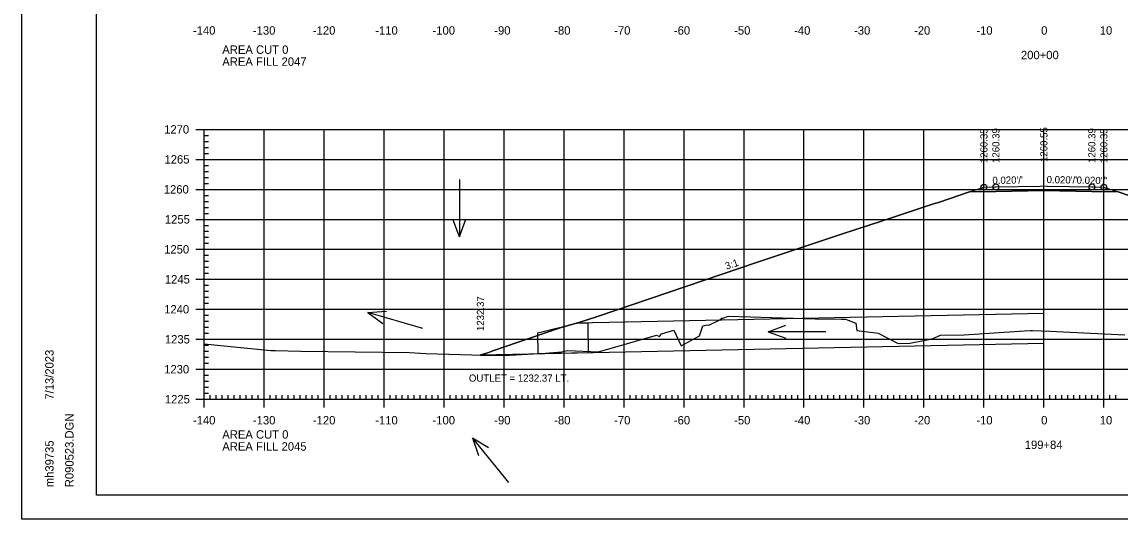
# Model space of a CAD drawing. Extents: x 1406028 to 1412453, y 321733 to 325986.
# Drawn here: x 1408884.4 to 1409067.5, y 322056.2 to 322139.1 of the extents above; entities that cross this region are included whole.
import ezdxf

# ---------------------------------------------------------------- set-up
doc = ezdxf.new("R2010")
doc.units = 0
for name, color, linetype in [('1', 7, 'Continuous'), ('R_Alt Surface', 7, 'Continuous'), ('R_Axis', 7, 'Continuous'), ('R_Axis Annot', 7, 'Continuous'), ('R_Border', 7, 'Continuous'), ('R_Exist Surface', 7, 'Continuous'), ('R_Fin Surface', 7, 'Continuous'), ('R_Fin Surface Annot', 7, 'Continuous'), ('R_Grid', 7, 'Continuous'), ('R_Horz Alg Annot', 7, 'Continuous'), ('R_No Plot', 7, 'Continuous'), ('R_Water', 7, 'Continuous'), ('R_Water Annot', 7, 'Continuous')]:
    doc.layers.add(name, color=color, linetype=linetype)

msp = doc.modelspace()

# ---------------------------------------------------------------- linework, layer by layer
at = {"layer": '1'}
msp.add_lwpolyline([(1408978.74, 322088.95), (1408978.84, 322083.95), (1408970.51, 322083.78), (1408970.44, 322087.28), (1408976.91, 322088.91)], close=True, dxfattribs=at)
at = {"layer": 'R_Alt Surface'}
msp.add_lwpolyline([(1409042.42, 322110.77), (1409046.81, 322110.86), (1409054.81, 322111.02), (1409062.81, 322110.86), (1409067.21, 322110.77)], dxfattribs=at)
at = {"layer": 'R_Axis'}
for p, q in [((1408913.41, 322121.21), (1408916.21, 322121.21)), ((1408914.81, 322076.21), (1408914.81, 322121.21)), ((1408914.81, 322120.21), (1408915.51, 322120.21)), ((1408914.81, 322119.21), (1408915.51, 322119.21)), ((1408914.81, 322118.21), (1408915.51, 322118.21)), ((1408914.81, 322117.21), (1408915.51, 322117.21)), ((1408913.41, 322116.21), (1408916.21, 322116.21)), ((1408914.81, 322115.21), (1408915.51, 322115.21)), ((1408914.81, 322114.21), (1408915.51, 322114.21)), ((1408914.81, 322113.21), (1408915.51, 322113.21)), ((1408914.81, 322112.21), (1408915.51, 322112.21)), ((1408913.41, 322111.21), (1408916.21, 322111.21)), ((1408914.81, 322110.21), (1408915.51, 322110.21)), ((1408914.81, 322109.21), (1408915.51, 322109.21)), ((1408914.81, 322108.21), (1408915.51, 322108.21)), ((1408913.41, 322106.21), (1408916.21, 322106.21)), ((1408914.81, 322107.21), (1408915.51, 322107.21)), ((1408914.81, 322105.21), (1408915.51, 322105.21)), ((1408914.81, 322104.21), (1408915.51, 322104.21)), ((1408914.81, 322103.21), (1408915.51, 322103.21)), ((1408913.41, 322101.21), (1408916.21, 322101.21)), ((1408914.81, 322102.21), (1408915.51, 322102.21)), ((1408914.81, 322100.21), (1408915.51, 322100.21)), ((1408914.81, 322099.21), (1408915.51, 322099.21)), ((1408914.81, 322098.21), (1408915.51, 322098.21)), ((1408914.81, 322097.21), (1408915.51, 322097.21)), ((1408913.41, 322096.21), (1408916.21, 322096.21)), ((1408914.81, 322095.21), (1408915.51, 322095.21)), ((1408914.81, 322094.21), (1408915.51, 322094.21)), ((1408914.81, 322093.21), (1408915.51, 322093.21)), ((1408914.81, 322092.21), (1408915.51, 322092.21)), ((1408913.41, 322091.21), (1408916.21, 322091.21)), ((1408914.81, 322090.21), (1408915.51, 322090.21)), ((1408914.81, 322089.21), (1408915.51, 322089.21)), ((1408914.81, 322088.21), (1408915.51, 322088.21)), ((1408913.41, 322086.21), (1408916.21, 322086.21)), ((1408914.81, 322087.21), (1408915.51, 322087.21)), ((1408914.81, 322085.21), (1408915.51, 322085.21)), ((1408914.81, 322084.21), (1408915.51, 322084.21)), ((1408914.81, 322083.21), (1408915.51, 322083.21)), ((1408913.41, 322081.21), (1408916.21, 322081.21)), ((1408914.81, 322082.21), (1408915.51, 322082.21)), ((1408914.81, 322080.21), (1408915.51, 322080.21)), ((1408914.81, 322079.21), (1408915.51, 322079.21)), ((1408914.81, 322078.21), (1408915.51, 322078.21)), ((1408914.81, 322074.81), (1408914.81, 322077.61)), ((1408914.81, 322077.21), (1408915.51, 322077.21)), ((1408915.81, 322076.21), (1408915.81, 322076.91)), ((1408916.81, 322076.21), (1408916.81, 322076.91)), ((1408917.81, 322076.21), (1408917.81, 322076.91)), ((1408918.81, 322076.21), (1408918.81, 322076.91)), ((1408919.81, 322076.21), (1408919.81, 322076.91)), ((1408920.81, 322076.21), (1408920.81, 322076.91)), ((1408921.81, 322076.21), (1408921.81, 322076.91)), ((1408922.81, 322076.21), (1408922.81, 322076.91)), ((1408923.81, 322076.21), (1408923.81, 322076.91)), ((1408924.81, 322074.81), (1408924.81, 322077.61)), ((1408925.81, 322076.21), (1408925.81, 322076.91)), ((1408926.81, 322076.21), (1408926.81, 322076.91)), ((1408927.81, 322076.21), (1408927.81, 322076.91)), ((1408928.81, 322076.21), (1408928.81, 322076.91)), ((1408929.81, 322076.21), (1408929.81, 322076.91)), ((1408930.81, 322076.21), (1408930.81, 322076.91)), ((1408931.81, 322076.21), (1408931.81, 322076.91)), ((1408932.81, 322076.21), (1408932.81, 322076.91)), ((1408933.81, 322076.21), (1408933.81, 322076.91)), ((1408934.81, 322074.81), (1408934.81, 322077.61)), ((1408935.81, 322076.21), (1408935.81, 322076.91)), ((1408936.81, 322076.21), (1408936.81, 322076.91)), ((1408937.81, 322076.21), (1408937.81, 322076.91)), ((1408938.81, 322076.21), (1408938.81, 322076.91)), ((1408939.81, 322076.21), (1408939.81, 322076.91)), ((1408940.81, 322076.21), (1408940.81, 322076.91)), ((1408941.81, 322076.21), (1408941.81, 322076.91)), ((1408942.81, 322076.21), (1408942.81, 322076.91)), ((1408943.81, 322076.21), (1408943.81, 322076.91)), ((1408944.81, 322074.81), (1408944.81, 322077.61)), ((1408945.81, 322076.21), (1408945.81, 322076.91)), ((1408946.81, 322076.21), (1408946.81, 322076.91)), ((1408947.81, 322076.21), (1408947.81, 322076.91)), ((1408948.81, 322076.21), (1408948.81, 322076.91)), ((1408949.81, 322076.21), (1408949.81, 322076.91)), ((1408950.81, 322076.21), (1408950.81, 322076.91)), ((1408951.81, 322076.21), (1408951.81, 322076.91)), ((1408952.81, 322076.21), (1408952.81, 322076.91)), ((1408953.81, 322076.21), (1408953.81, 322076.91)), ((1408954.81, 322074.81), (1408954.81, 322077.61)), ((1408955.81, 322076.21), (1408955.81, 322076.91)), ((1408956.81, 322076.21), (1408956.81, 322076.91)), ((1408957.81, 322076.21), (1408957.81, 322076.91)), ((1408958.81, 322076.21), (1408958.81, 322076.91)), ((1408959.81, 322076.21), (1408959.81, 322076.91)), ((1408960.81, 322076.21), (1408960.81, 322076.91)), ((1408961.81, 322076.21), (1408961.81, 322076.91)), ((1408962.81, 322076.21), (1408962.81, 322076.91)), ((1408963.81, 322076.21), (1408963.81, 322076.91)), ((1408964.81, 322074.81), (1408964.81, 322077.61)), ((1408965.81, 322076.21), (1408965.81, 322076.91)), ((1408966.81, 322076.21), (1408966.81, 322076.91)), ((1408967.81, 322076.21), (1408967.81, 322076.91)), ((1408968.81, 322076.21), (1408968.81, 322076.91)), ((1408969.81, 322076.21), (1408969.81, 322076.91)), ((1408970.81, 322076.21), (1408970.81, 322076.91)), ((1408971.81, 322076.21), (1408971.81, 322076.91)), ((1408972.81, 322076.21), (1408972.81, 322076.91)), ((1408973.81, 322076.21), (1408973.81, 322076.91)), ((1408974.81, 322074.81), (1408974.81, 322077.61)), ((1408975.81, 322076.21), (1408975.81, 322076.91)), ((1408976.81, 322076.21), (1408976.81, 322076.91)), ((1408977.81, 322076.21), (1408977.81, 322076.91)), ((1408978.81, 322076.21), (1408978.81, 322076.91)), ((1408979.81, 322076.21), (1408979.81, 322076.91)), ((1408980.81, 322076.21), (1408980.81, 322076.91)), ((1408981.81, 322076.21), (1408981.81, 322076.91)), ((1408982.81, 322076.21), (1408982.81, 322076.91)), ((1408983.81, 322076.21), (1408983.81, 322076.91)), ((1408984.81, 322074.81), (1408984.81, 322077.61)), ((1408985.81, 322076.21), (1408985.81, 322076.91)), ((1408986.81, 322076.21), (1408986.81, 322076.91)), ((1408987.81, 322076.21), (1408987.81, 322076.91)), ((1408988.81, 322076.21), (1408988.81, 322076.91)), ((1408989.81, 322076.21), (1408989.81, 322076.91)), ((1408990.81, 322076.21), (1408990.81, 322076.91)), ((1408991.81, 322076.21), (1408991.81, 322076.91)), ((1408992.81, 322076.21), (1408992.81, 322076.91)), ((1408993.81, 322076.21), (1408993.81, 322076.91)), ((1408994.81, 322074.81), (1408994.81, 322077.61)), ((1408995.81, 322076.21), (1408995.81, 322076.91)), ((1408996.81, 322076.21), (1408996.81, 322076.91)), ((1408997.81, 322076.21), (1408997.81, 322076.91)), ((1408998.81, 322076.21), (1408998.81, 322076.91)), ((1408999.81, 322076.21), (1408999.81, 322076.91)), ((1409000.81, 322076.21), (1409000.81, 322076.91)), ((1409001.81, 322076.21), (1409001.81, 322076.91)), ((1409002.81, 322076.21), (1409002.81, 322076.91)), ((1409003.81, 322076.21), (1409003.81, 322076.91)), ((1409004.81, 322074.81), (1409004.81, 322077.61)), ((1409005.81, 322076.21), (1409005.81, 322076.91)), ((1409006.81, 322076.21), (1409006.81, 322076.91)), ((1409007.81, 322076.21), (1409007.81, 322076.91)), ((1409008.81, 322076.21), (1409008.81, 322076.91)), ((1409009.81, 322076.21), (1409009.81, 322076.91)), ((1409010.81, 322076.21), (1409010.81, 322076.91)), ((1409011.81, 322076.21), (1409011.81, 322076.91)), ((1409012.81, 322076.21), (1409012.81, 322076.91)), ((1409013.81, 322076.21), (1409013.81, 322076.91)), ((1409014.81, 322074.81), (1409014.81, 322077.61)), ((1409015.81, 322076.21), (1409015.81, 322076.91)), ((1409016.81, 322076.21), (1409016.81, 322076.91)), ((1409017.81, 322076.21), (1409017.81, 322076.91)), ((1409018.81, 322076.21), (1409018.81, 322076.91)), ((1409019.81, 322076.21), (1409019.81, 322076.91)), ((1409020.81, 322076.21), (1409020.81, 322076.91)), ((1409021.81, 322076.21), (1409021.81, 322076.91)), ((1409022.81, 322076.21), (1409022.81, 322076.91)), ((1409023.81, 322076.21), (1409023.81, 322076.91)), ((1409024.81, 322074.81), (1409024.81, 322077.61)), ((1409025.81, 322076.21), (1409025.81, 322076.91)), ((1409026.81, 322076.21), (1409026.81, 322076.91)), ((1409027.81, 322076.21), (1409027.81, 322076.91)), ((1409028.81, 322076.21), (1409028.81, 322076.91)), ((1409029.81, 322076.21), (1409029.81, 322076.91)), ((1409030.81, 322076.21), (1409030.81, 322076.91)), ((1409031.81, 322076.21), (1409031.81, 322076.91)), ((1409032.81, 322076.21), (1409032.81, 322076.91)), ((1409033.81, 322076.21), (1409033.81, 322076.91)), ((1409034.81, 322074.81), (1409034.81, 322077.61)), ((1409035.81, 322076.21), (1409035.81, 322076.91)), ((1409036.81, 322076.21), (1409036.81, 322076.91)), ((1409037.81, 322076.21), (1409037.81, 322076.91)), ((1409038.81, 322076.21), (1409038.81, 322076.91)), ((1409039.81, 322076.21), (1409039.81, 322076.91)), ((1409040.81, 322076.21), (1409040.81, 322076.91)), ((1409041.81, 322076.21), (1409041.81, 322076.91)), ((1409042.81, 322076.21), (1409042.81, 322076.91)), ((1409043.81, 322076.21), (1409043.81, 322076.91)), ((1409044.81, 322074.81), (1409044.81, 322077.61)), ((1409045.81, 322076.21), (1409045.81, 322076.91)), ((1409046.81, 322076.21), (1409046.81, 322076.91)), ((1409047.81, 322076.21), (1409047.81, 322076.91)), ((1409048.81, 322076.21), (1409048.81, 322076.91)), ((1409049.81, 322076.21), (1409049.81, 322076.91)), ((1409050.81, 322076.21), (1409050.81, 322076.91)), ((1409051.81, 322076.21), (1409051.81, 322076.91)), ((1409052.81, 322076.21), (1409052.81, 322076.91)), ((1409053.81, 322076.21), (1409053.81, 322076.91)), ((1409054.81, 322074.81), (1409054.81, 322077.61)), ((1409055.81, 322076.21), (1409055.81, 322076.91)), ((1409056.81, 322076.21), (1409056.81, 322076.91)), ((1409057.81, 322076.21), (1409057.81, 322076.91)), ((1409058.81, 322076.21), (1409058.81, 322076.91)), ((1409059.81, 322076.21), (1409059.81, 322076.91)), ((1409060.81, 322076.21), (1409060.81, 322076.91)), ((1409061.81, 322076.21), (1409061.81, 322076.91)), ((1409062.81, 322076.21), (1409062.81, 322076.91)), ((1409063.81, 322076.21), (1409063.81, 322076.91)), ((1409064.81, 322074.81), (1409064.81, 322077.61)), ((1409065.81, 322076.21), (1409065.81, 322076.91)), ((1409066.81, 322076.21), (1409066.81, 322076.91)), ((1408913.41, 322076.21), (1408916.21, 322076.21)), ((1408914.81, 322076.21), (1409194.81, 322076.21))]:
    msp.add_line(p, q, dxfattribs=at)
at = {"layer": 'R_Border'}
for p, q in [((1408896.81, 322060.21), (1408896.81, 322265.67)), ((1408896.81, 322060.21), (1408896.81, 322060.21)), ((1409212.99, 322060.21), (1408896.81, 322060.21))]:
    msp.add_line(p, q, dxfattribs=at)
at = {"layer": 'R_Exist Surface'}
msp.add_lwpolyline([(1408914.81, 322085.46), (1408925.9, 322084.34), (1408926.06, 322084.33), (1408926.64, 322084.32), (1408930.9, 322084.22), (1408949.01, 322083.99), (1408951.75, 322083.83), (1408959.41, 322083.61), (1408964.78, 322083.51), (1408971.73, 322083.9), (1408974.4, 322084.09), (1408975.4, 322084.31), (1408980.56, 322084.11), (1408990.24, 322086.88), (1408990.72, 322086.68), (1408991.03, 322087.13), (1408993.12, 322087.74), (1408994.35, 322085.13), (1408997.41, 322086.81), (1408997.93, 322088.47), (1408998.72, 322088.6), (1408998.97, 322088.57), (1409000.75, 322089.45), (1409001.09, 322089.74), (1409001.25, 322089.75), (1409002.25, 322090.04), (1409016.65, 322089.62), (1409021.07, 322089.59), (1409021.74, 322089.54), (1409022.2, 322089.39), (1409023.43, 322088.87), (1409023.63, 322087.67), (1409026.37, 322087.34), (1409027.19, 322087.22), (1409030.52, 322085.52), (1409032.48, 322085.55), (1409036.16, 322086.27), (1409037.55, 322086.9), (1409041.54, 322086.96), (1409051.54, 322087.6), (1409052.6, 322087.67), (1409052.92, 322087.68), (1409055.82, 322087.54), (1409068.3, 322086.97)], dxfattribs=at)
at = {"layer": 'R_Fin Surface'}
msp.add_lwpolyline([(1408960.86, 322083.58), (1408960.89, 322083.59), (1408961.31, 322083.72), (1408961.49, 322083.78), (1408962.1, 322083.97), (1408962.94, 322084.28), (1408971.4, 322087.18), (1408974.16, 322088.09), (1408977.42, 322089.06), (1408980.19, 322089.96), (1409007.08, 322099.07), (1409009.56, 322099.91), (1409013.07, 322101.08), (1409016.06, 322102.07), (1409017.59, 322102.57), (1409020.92, 322103.67), (1409023.64, 322104.56), (1409027.75, 322105.92), (1409036.08, 322108.66), (1409036.81, 322108.9), (1409037.22, 322109.04), (1409042.42, 322110.77), (1409044.63, 322111.51), (1409044.81, 322111.57), (1409046.66, 322111.61), (1409046.81, 322111.61), (1409054.2, 322111.76), (1409054.81, 322111.77), (1409055.38, 322111.76), (1409062.81, 322111.61), (1409062.96, 322111.61), (1409064.81, 322111.57), (1409067.03, 322110.83), (1409067.21, 322110.77), (1409072.39, 322109.04)], dxfattribs=at)
at = {"layer": 'R_Grid'}
for p, q in [((1408914.81, 322121.21), (1409194.81, 322121.21)), ((1408914.81, 322076.21), (1408914.81, 322121.21)), ((1408924.81, 322076.21), (1408924.81, 322121.21)), ((1408934.81, 322076.21), (1408934.81, 322121.21)), ((1408944.81, 322076.21), (1408944.81, 322121.21)), ((1408954.81, 322076.21), (1408954.81, 322121.21)), ((1408964.81, 322076.21), (1408964.81, 322121.21)), ((1408974.81, 322076.21), (1408974.81, 322121.21)), ((1408984.81, 322076.21), (1408984.81, 322121.21)), ((1408994.81, 322076.21), (1408994.81, 322121.21)), ((1409004.81, 322076.21), (1409004.81, 322121.21)), ((1409014.81, 322076.21), (1409014.81, 322121.21)), ((1409024.81, 322076.21), (1409024.81, 322121.21)), ((1409034.81, 322076.21), (1409034.81, 322121.21)), ((1409044.81, 322076.21), (1409044.81, 322121.21)), ((1409054.81, 322076.21), (1409054.81, 322121.21)), ((1409064.81, 322076.21), (1409064.81, 322121.21)), ((1408914.81, 322116.21), (1409194.81, 322116.21)), ((1408914.81, 322111.21), (1409194.81, 322111.21)), ((1408914.81, 322106.21), (1409194.81, 322106.21)), ((1408914.81, 322101.21), (1409194.81, 322101.21)), ((1408914.81, 322096.21), (1409194.81, 322096.21)), ((1408914.81, 322091.21), (1409194.81, 322091.21)), ((1408914.81, 322086.21), (1409194.81, 322086.21)), ((1408914.81, 322081.21), (1409194.81, 322081.21)), ((1408914.81, 322076.21), (1409194.81, 322076.21))]:
    msp.add_line(p, q, dxfattribs=at)
at = {"layer": 'R_No Plot'}
msp.add_line((1408884.41, 322056.24), (1409217.75, 322056.24), dxfattribs=at)
for points in [[(1408884.41, 322269.57), (1409217.75, 322269.57), (1409217.75, 322056.23), (1408884.41, 322056.23)], [(1409130.73, 322265.67), (1409150.35, 322265.67), (1409150.35, 322255.79), (1409166.47, 322255.79), (1409189.67, 322255.79), (1409189.67, 322231.46), (1409212.99, 322231.46), (1409212.99, 322060.21), (1408896.81, 322060.21), (1408896.81, 322265.67)]]:
    msp.add_lwpolyline(points, close=True, dxfattribs=at)
msp.add_lwpolyline([(1409072.39, 322109.04), (1409067.21, 322110.77), (1409062.81, 322110.86), (1409054.81, 322111.02), (1409046.81, 322110.86), (1409042.42, 322110.77), (1409037.22, 322109.04), (1409036.81, 322108.9), (1409036.08, 322108.66), (1409027.75, 322105.92), (1409023.64, 322104.56), (1409020.92, 322103.67), (1409017.59, 322102.57), (1409016.06, 322102.07), (1409013.07, 322101.08), (1409009.56, 322099.91), (1409007.08, 322099.07), (1408980.19, 322089.96), (1408977.42, 322089.06), (1408974.16, 322088.09), (1408971.4, 322087.18), (1408962.94, 322084.28), (1408962.1, 322083.97), (1408961.49, 322083.78), (1408961.31, 322083.72), (1408960.89, 322083.59), (1408960.86, 322083.58), (1408964.78, 322083.51), (1408971.73, 322083.9), (1408974.4, 322084.09), (1408975.4, 322084.31), (1408980.56, 322084.11), (1408990.24, 322086.88), (1408990.72, 322086.68), (1408991.03, 322087.13), (1408993.12, 322087.74), (1408994.35, 322085.13), (1408997.41, 322086.81), (1408997.93, 322088.47), (1408998.72, 322088.6), (1408998.97, 322088.57), (1409000.75, 322089.45), (1409001.09, 322089.74), (1409001.25, 322089.75), (1409002.25, 322090.04), (1409016.65, 322089.62), (1409021.07, 322089.59), (1409021.74, 322089.54), (1409022.2, 322089.39), (1409023.43, 322088.87), (1409023.63, 322087.67), (1409026.37, 322087.34), (1409027.19, 322087.22), (1409030.52, 322085.52), (1409032.48, 322085.55), (1409036.16, 322086.27), (1409037.55, 322086.9), (1409041.54, 322086.96), (1409051.54, 322087.6), (1409052.6, 322087.67), (1409052.92, 322087.68), (1409055.82, 322087.54), (1409068.3, 322086.97)], dxfattribs=at)
for centre in [(1409044.81, 322111.57), (1409046.81, 322111.61), (1409062.81, 322111.61), (1409064.81, 322111.57)]:
    msp.add_circle(centre, 0.5, dxfattribs=at)
at = {"layer": 'R_Water'}
for p, q in [((1409054.81, 322090.49), (1408976.95, 322088.91)), ((1409054.81, 322085.49), (1408960.86, 322083.58))]:
    msp.add_line(p, q, dxfattribs=at)
at = {"layer": 'R_Water Annot'}
for p, q in [((1408957.34, 322112.86), (1408957.34, 322103.29)), ((1408957.34, 322103.29), (1408956.28, 322106.22)), ((1408957.34, 322103.29), (1408958.41, 322106.22)), ((1408942.06, 322090.65), (1408945.17, 322090.87)), ((1408951.26, 322088.02), (1408942.06, 322090.65)), ((1408942.06, 322090.65), (1408944.58, 322088.82)), ((1409008.86, 322087.47), (1409011.79, 322088.54)), ((1409018.44, 322087.47), (1409008.86, 322087.47)), ((1409008.86, 322087.47), (1409011.79, 322086.41)), ((1408965.57, 322062.34), (1408959.52, 322069.75)), ((1408959.52, 322069.75), (1408962.2, 322068.16)), ((1408959.52, 322069.75), (1408960.54, 322066.81))]:
    msp.add_line(p, q, dxfattribs=at)

# ---------------------------------------------------------------- texts
at = {"layer": 'R_Axis Annot'}
for s, p in [('-140', (1408912.92, 322137.01)), ('-130', (1408922.92, 322137.01)), ('-120', (1408932.92, 322137.01)), ('-110', (1408943.32, 322137.01)), ('-100', (1408952.87, 322137.01)), ('-90', (1408963.16, 322137.01)), ('-80', (1408973.16, 322137.01)), ('-70', (1408983.16, 322137.01)), ('-60', (1408993.12, 322137.01)), ('-50', (1409003.16, 322137.01)), ('-40', (1409013.16, 322137.01)), ('-30', (1409023.16, 322137.01)), ('-20', (1409033.16, 322137.01)), ('-10', (1409043.55, 322137.01)), ('0', (1409054.36, 322137.01)), ('10', (1409064.13, 322137.01)), ('AREA CUT 0', (1408917.81, 322133.81)), ('200+00', (1409050.99, 322132.91)), ('AREA FILL 2047', (1408917.81, 322131.81)), ('1270', (1408908.12, 322120.51)), ('1265', (1408908.18, 322115.51)), ('1260', (1408908.06, 322110.51)), ('1255', (1408908.24, 322105.51)), ('1250', (1408908.12, 322100.51)), ('1245', (1408908.24, 322095.51)), ('1240', (1408908.12, 322090.51)), ('1235', (1408908.24, 322085.51)), ('1230', (1408908.12, 322080.51)), ('1225', (1408908.24, 322075.51)), ('-140', (1408912.92, 322072.01)), ('-130', (1408922.92, 322072.01)), ('-120', (1408932.92, 322072.01)), ('-110', (1408943.32, 322072.01)), ('-100', (1408952.87, 322072.01)), ('-90', (1408963.16, 322072.01)), ('-80', (1408973.16, 322072.01)), ('-70', (1408983.16, 322072.01)), ('-60', (1408993.12, 322072.01)), ('-50', (1409003.16, 322072.01)), ('-40', (1409013.16, 322072.01)), ('-30', (1409023.16, 322072.01)), ('-20', (1409033.16, 322072.01)), ('-10', (1409043.55, 322072.01)), ('0', (1409054.36, 322072.01)), ('10', (1409064.13, 322072.01)), ('AREA CUT 0', (1408917.81, 322069.64)), ('AREA FILL 2045', (1408917.81, 322067.64)), ('199+84', (1409051.62, 322067.91))]:
    msp.add_text(s, height=1.4, dxfattribs=at).set_placement(p)
at = {"layer": 'R_Border'}
for s, p in [('7/13/2023', (1408889.68, 322076.14)), ('R090523.DGN', (1408893.01, 322061.54)), ('mh39735', (1408889.68, 322061.54))]:
    msp.add_text(s, height=1.4, rotation=90, dxfattribs=at).set_placement(p)
at = {"layer": 'R_Fin Surface Annot'}
for s, rotation, p in [('1260.35', 90, (1409045.41, 322115.57)), ('1260.39', 90, (1409047.41, 322115.61)), ('1260.55', 90, (1409055.41, 322115.77)), ('1260.39', 90, (1409063.41, 322115.61)), ('1260.35', 90, (1409065.41, 322115.57)), ("0.020'/'", 1.1458, (1409046.24, 322112.1)), ("0.020'/'", 358.8542, (1409055.26, 322112.26)), ("0.020'/'", 358.8542, (1409060.26, 322112.16)), ('3:1', 18.4351, (1409001.89, 322097.79)), ('1232.37', 90, (1408961.46, 322087.58))]:
    msp.add_text(s, height=1.2, rotation=rotation, dxfattribs=at).set_placement(p)
at = {"layer": 'R_Horz Alg Annot'}
msp.add_text('OUTLET = 1232.37 LT.', height=1.2, dxfattribs=at).set_placement((1408958.93, 322079.14))

doc.saveas('drawing.dxf')
